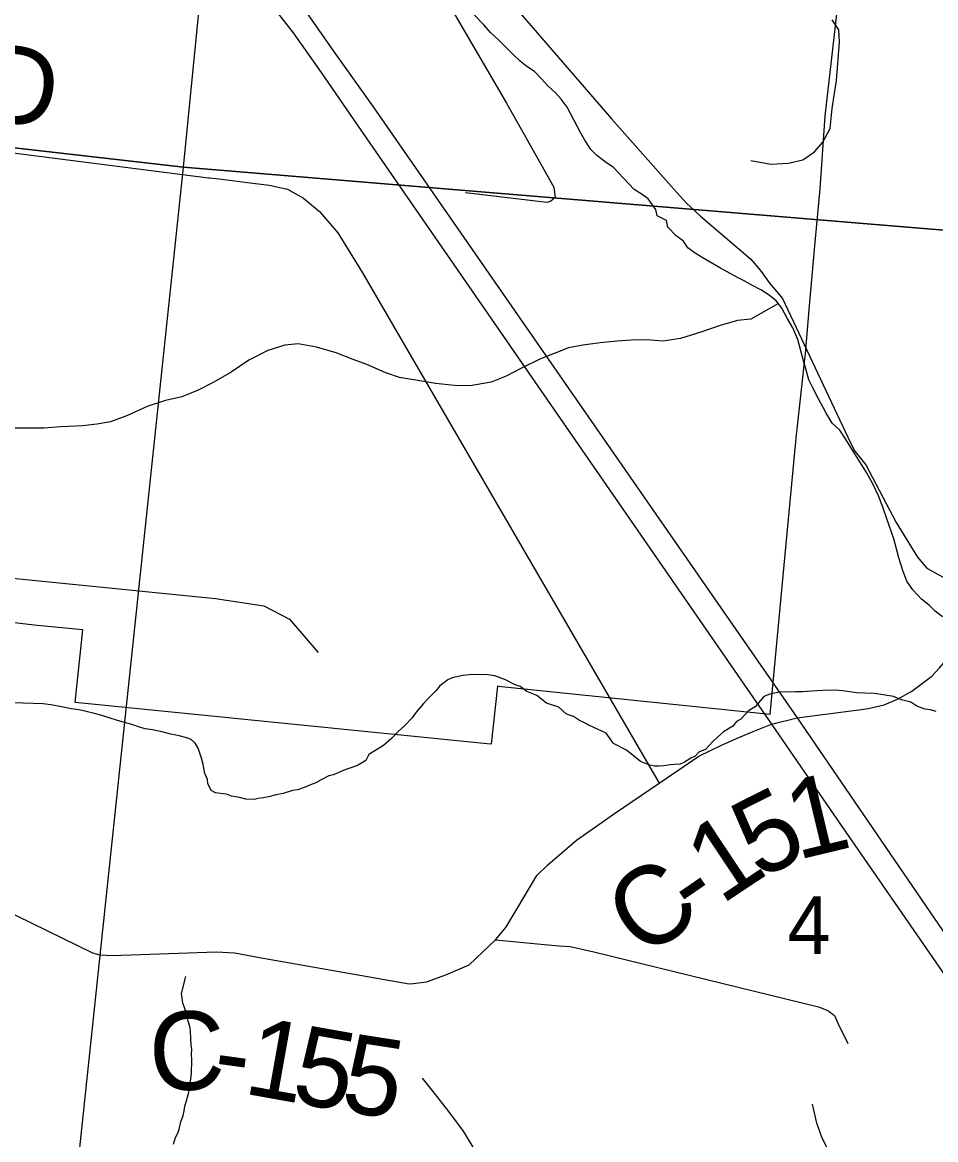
# Model space of a CAD drawing. Extents: x -8.2 to 38.5, y -0.1 to 21.9.
# Drawn here: x 2.824 to 3.486, y 18.678 to 19.487 of the extents above; entities that cross this region are included whole.
import ezdxf

# ---------------------------------------------------------------- set-up
doc = ezdxf.new("R2010")
doc.units = 0
for name, color, linetype in [('Default', 7, 'Continuous'), ('GM_X_Adjacent_County_Text', 7, 'Continuous'), ('GM_X_Airport_Location_Class_2', 7, 'Continuous'), ('GM_X_Airport_Location_Class_3', 7, 'Continuous'), ('GM_X_County_Road_Text', 7, 'Continuous'), ('GM_X_Minor_Lake', 7, 'Continuous'), ('GM_X_Minor_River', 7, 'Continuous'), ('GM_X_State_Location', 7, 'Continuous'), ('GM_X_Township_Subdivision_Text', 7, 'Continuous'), ('GM_X_Township_Text', 7, 'Continuous')]:
    doc.layers.add(name, color=color, linetype=linetype)

msp = doc.modelspace()

# ---------------------------------------------------------------- linework, layer by layer
at = {"layer": 'Default'}
for points in [[(2.16338, 20.48187), (2.16338, 19.47123), (2.94081, 19.38227), (3.04131, 20.39747)], [(2.16338, 19.47123), (2.16338, 18.47186), (2.83734, 18.40237), (2.94081, 19.38227)]]:
    msp.add_lwpolyline(points, close=True, dxfattribs=at)
msp.add_lwpolyline([(3.41379, 19.493), (3.40549, 19.41911), (3.40175, 19.36666), (3.39768, 19.32267), (3.39595, 19.30346), (3.39387, 19.27927), (3.39109, 19.24707), (3.39066, 19.24312), (3.38508, 19.19243), (3.38488, 19.19062), (3.38444, 19.18668), (3.38409, 19.18291), (3.3839, 19.18094), (3.3767, 19.10439), (3.36555, 18.98579), (3.17114, 19.0059), (3.16831, 19.00619), (3.16369, 18.96422), (3.16086, 18.9645), (2.86227, 18.99442), (2.86786, 19.04702), (2.83497, 19.05032), (2.79953, 19.05424)], dxfattribs=at)
at = {"layer": 'GM_X_Adjacent_County_Text'}
for points in [[(3.04131, 20.39747), (4.03667, 20.29136), (3.94314, 19.29912), (2.94081, 19.38227)], [(3.94314, 19.29912), (3.84833, 18.30047), (2.83734, 18.40237), (2.94081, 19.38227)]]:
    msp.add_lwpolyline(points, close=True, dxfattribs=at)
at = {"layer": 'GM_X_Airport_Location_Class_2'}
for points in [[(3.35186, 19.38711), (3.36624, 19.38455), (3.37908, 19.38506), (3.38962, 19.38763), (3.39784, 19.39328), (3.40401, 19.40047), (3.4094, 19.41024), (3.41069, 19.42488), (3.41377, 19.44518), (3.41608, 19.47292), (3.41557, 19.48166), (3.41069, 19.48911)], [(2.59965, 19.05086), (2.62209, 19.0486), (2.63274, 19.04912), (2.6407, 19.05509), (2.66855, 19.08383), (2.68355, 19.09182), (2.69711, 19.0964), (2.71187, 19.0964), (2.77842, 19.08832), (2.95204, 19.07106)], [(2.95204, 19.07106), (2.96401, 19.06987), (2.99912, 19.06443), (3.01761, 19.05493), (3.03842, 19.03078)]]:
    msp.add_lwpolyline(points, dxfattribs=at)
at = {"layer": 'GM_X_Airport_Location_Class_3'}
for points in [[(2.51015, 19.91355), (2.55411, 19.89008), (2.59469, 19.86662), (2.63548, 19.84074), (2.67343, 19.81573), (2.71422, 19.787), (2.74625, 19.76222), (2.77936, 19.73568), (2.81248, 19.70782), (2.83902, 19.6837), (2.88245, 19.6418), (2.9, 19.62338), (2.92789, 19.59381), (2.94605, 19.57206), (2.9693, 19.54486), (2.99496, 19.51218), (3.02019, 19.4795), (3.04058, 19.45077), (3.06668, 19.41304), (3.36682, 18.97876), (3.4094, 18.91703)], [(3.4094, 18.91703), (3.54394, 18.72194), (3.6115, 18.62456), (3.80034, 18.35105), (3.84376, 18.28895), (3.8839, 18.23152), (3.90386, 18.2052), (3.92843, 18.17844), (3.94926, 18.15958), (3.97164, 18.14225), (3.99927, 18.12427), (4.03722, 18.10519), (4.06573, 18.094), (4.08985, 18.08654), (4.12385, 18.07909), (4.15214, 18.07558), (4.18397, 18.07447), (4.18884, 18.07473)]]:
    msp.add_lwpolyline(points, dxfattribs=at)
at = {"layer": 'GM_X_Minor_River'}
for points in [[(3.3107, 19.32035), (3.30623, 19.3239), (3.30294, 19.32857), (3.29772, 19.33252), (3.2918, 19.33878), (3.2908, 19.34375), (3.28404, 19.34699), (3.28302, 19.35159), (3.27753, 19.35935), (3.27305, 19.36252), (3.26744, 19.36611), (3.25228, 19.38214), (3.2463, 19.38612), (3.24035, 19.39085), (3.2359, 19.39516), (3.23152, 19.40176), (3.22861, 19.40679), (3.22138, 19.4207), (3.21885, 19.42572), (3.21445, 19.43155), (3.21039, 19.43623), (3.20444, 19.44135), (3.20038, 19.44603), (3.19521, 19.45151), (3.1896, 19.45509), (3.18476, 19.45903), (3.17995, 19.46374), (3.1755, 19.46805), (3.1692, 19.47432), (3.16327, 19.47981), (3.15847, 19.48528), (3.15145, 19.49271)], [(3.49067, 19.05641), (3.48547, 19.06074), (3.48102, 19.06506), (3.47543, 19.0694), (3.46915, 19.07605), (3.46475, 19.08226), (3.46192, 19.08996), (3.45913, 19.09918), (3.4574, 19.1057), (3.45531, 19.11299), (3.45215, 19.1226), (3.45038, 19.1276), (3.44757, 19.13605), (3.44437, 19.14414), (3.44005, 19.1534), (3.4357, 19.16113), (3.42039, 19.18555), (3.41637, 19.19175), (3.4108, 19.19686), (3.40607, 19.20461), (3.40065, 19.21504), (3.39666, 19.22238), (3.39377, 19.22817), (3.39171, 19.23623), (3.38996, 19.24199), (3.38582, 19.25733), (3.38224, 19.26581), (3.37825, 19.27278), (3.37426, 19.28012), (3.37023, 19.28556), (3.36501, 19.28952), (3.35903, 19.29349), (3.35265, 19.29672), (3.34704, 19.29992), (3.34216, 19.30234), (3.33466, 19.30636), (3.32979, 19.30916), (3.3223, 19.31356), (3.31669, 19.31676), (3.3107, 19.32035)], [(3.37177, 19.28348), (3.35181, 19.27206), (3.34229, 19.27115), (3.32967, 19.26765), (3.31626, 19.26304), (3.30094, 19.25809), (3.28835, 19.25612), (3.27621, 19.25717), (3.26519, 19.25706), (3.25491, 19.25617), (3.24272, 19.25495), (3.23014, 19.25335), (3.21984, 19.25132), (3.20948, 19.24739), (3.19951, 19.24345), (3.18566, 19.23657), (3.1745, 19.23076), (3.16376, 19.22645), (3.14849, 19.22378), (3.1371, 19.22406), (3.12345, 19.22554), (3.11362, 19.2273), (3.09734, 19.22998), (3.08754, 19.23326), (3.07363, 19.2393), (3.06384, 19.24297), (3.05141, 19.24783), (3.03708, 19.25198), (3.02383, 19.25421), (3.01431, 19.2533), (3.00205, 19.24942), (2.98821, 19.24253), (2.97546, 19.23372), (2.96274, 19.22642), (2.95158, 19.22061), (2.93969, 19.21595), (2.92784, 19.2132), (2.91444, 19.20897), (2.90022, 19.20247), (2.88795, 19.19782), (2.87803, 19.19617), (2.86774, 19.1949), (2.85214, 19.19414), (2.83958, 19.1933), (2.82742, 19.19322), (2.81564, 19.19313)], [(3.48616, 18.988), (3.48202, 18.98926), (3.47823, 18.98974), (3.4722, 18.99181), (3.46771, 18.99461), (3.46091, 18.99632), (3.45527, 18.99876), (3.4477, 19.00011), (3.44126, 19.00105), (3.42835, 19.00142), (3.42494, 19.00189), (3.42191, 19.00236), (3.4185, 19.00283), (3.41281, 19.00337), (3.40368, 19.00325), (3.39606, 19.0027), (3.3892, 19.00213), (3.38426, 19.00227), (3.37931, 19.00203), (3.37589, 19.00212), (3.37246, 19.00184), (3.36558, 19.00051), (3.36134, 18.99872), (3.3586, 18.99575), (3.35506, 18.99128), (3.35004, 18.98837), (3.34455, 18.98244), (3.34146, 18.98062), (3.33871, 18.97727), (3.33214, 18.97326), (3.32746, 18.96921), (3.32395, 18.96588), (3.31925, 18.96068), (3.31425, 18.95853), (3.31151, 18.95556), (3.30842, 18.95413), (3.30378, 18.95121), (3.3007, 18.94977), (3.29651, 18.94951), (3.29346, 18.94922), (3.28888, 18.94858), (3.28507, 18.94831), (3.28203, 18.94839), (3.27787, 18.94927), (3.27185, 18.95172), (3.26181, 18.96), (3.25243, 18.96483), (3.24693, 18.97222), (3.23491, 18.97789), (3.23078, 18.97991), (3.22779, 18.98151), (3.2233, 18.9843), (3.2184, 18.98597), (3.21283, 18.99107), (3.20378, 18.99399), (3.19671, 18.99952), (3.18956, 19.00238), (3.18471, 19.00594), (3.18058, 19.00758), (3.1742, 19.01081), (3.16629, 19.0137), (3.16137, 19.01459), (3.15415, 19.0148), (3.14768, 19.0146), (3.1431, 19.01396), (3.13545, 19.01227), (3.13237, 19.01084), (3.12654, 19.00643), (3.12379, 19.00308), (3.11832, 18.99752), (3.1148, 18.99381), (3.1093, 18.98749), (3.10653, 18.98338), (3.10105, 18.97744), (3.09637, 18.97339), (3.09168, 18.96857), (3.08584, 18.9634), (3.07501, 18.95685), (3.07299, 18.95233), (3.0668, 18.9487), (3.05644, 18.94518), (3.04951, 18.94195), (3.04607, 18.94128), (3.04067, 18.93839), (3.03681, 18.93621), (3.03296, 18.9348), (3.02911, 18.933), (3.02336, 18.93126), (3.01992, 18.93059)], [(3.01992, 18.93059), (3.01302, 18.9285), (3.00805, 18.9275), (3.00231, 18.92613), (2.99849, 18.92548), (2.99505, 18.92481), (2.99199, 18.92414), (2.98591, 18.92431), (2.98138, 18.92558), (2.9757, 18.9265), (2.97194, 18.92812), (2.96777, 18.92862), (2.96398, 18.92911), (2.96098, 18.93072), (2.95846, 18.93574), (2.95816, 18.93879), (2.95637, 18.94303), (2.95503, 18.94954), (2.95401, 18.95414), (2.95155, 18.96144), (2.94936, 18.96493), (2.94639, 18.96768), (2.94338, 18.96891), (2.93771, 18.97021), (2.93166, 18.97152), (2.92524, 18.97322), (2.91844, 18.97455), (2.91314, 18.97546), (2.90823, 18.97674), (2.90409, 18.97838), (2.89918, 18.97966), (2.89314, 18.98135), (2.88711, 18.98343), (2.87994, 18.98553), (2.87541, 18.9868), (2.87126, 18.98768), (2.86748, 18.98855), (2.86332, 18.98942), (2.85953, 18.98991), (2.85121, 18.99167), (2.84629, 18.99256), (2.84288, 18.99304), (2.83909, 18.99353), (2.82465, 18.99393), (2.81781, 18.99412)], [(2.93352, 18.67444), (2.93517, 18.67935), (2.93678, 18.68235), (2.93762, 18.68537), (2.9389, 18.69067), (2.94055, 18.69519), (2.9414, 18.6986), (2.94187, 18.70201), (2.94311, 18.70578), (2.9444, 18.71108), (2.94524, 18.7141), (2.94534, 18.71791), (2.94621, 18.72169), (2.94671, 18.72625), (2.94696, 18.73538), (2.94669, 18.73958), (2.94678, 18.743), (2.94649, 18.74644), (2.94623, 18.75063), (2.94601, 18.75673), (2.94534, 18.7598), (2.94394, 18.7644), (2.94293, 18.76938), (2.94152, 18.77361), (2.94047, 18.77669), (2.93951, 18.78357), (2.94251, 18.79605)], [(3.15071, 18.67229), (3.14377, 18.68387), (3.1331, 18.6982), (3.12167, 18.71255), (3.11392, 18.72225)], [(3.40863, 18.66865), (3.4032, 18.67944), (3.39965, 18.68979), (3.39656, 18.70356)]]:
    msp.add_lwpolyline(points, dxfattribs=at)
at = {"layer": 'GM_X_State_Location'}
for points in [[(2.51015, 19.91355), (2.55411, 19.89008), (2.59469, 19.86662), (2.63548, 19.84074), (2.67343, 19.81573), (2.71422, 19.787), (2.74625, 19.76222), (2.77936, 19.73568), (2.81248, 19.70782), (2.83902, 19.6837), (2.88245, 19.6418), (2.9, 19.62338), (2.92789, 19.59381), (2.94605, 19.57206), (2.9693, 19.54486), (2.99496, 19.51218), (3.02019, 19.4795), (3.04058, 19.45077), (3.06668, 19.41304), (3.36682, 18.97876), (3.4094, 18.91703)], [(3.02994, 19.49441), (3.05011, 19.46568), (3.07819, 19.42598), (3.38547, 18.98337), (3.5583, 18.73049)], [(3.4094, 18.91703), (3.54394, 18.72194), (3.6115, 18.62456), (3.80034, 18.35105), (3.84376, 18.28895), (3.8839, 18.23152), (3.90386, 18.2052), (3.92843, 18.17844), (3.94926, 18.15958), (3.97164, 18.14225), (3.99927, 18.12427), (4.03722, 18.10519), (4.06573, 18.094), (4.08985, 18.08654), (4.12385, 18.07909), (4.15214, 18.07558), (4.18397, 18.07447), (4.18884, 18.07473)]]:
    msp.add_lwpolyline(points, dxfattribs=at)
at = {"layer": 'GM_X_Township_Subdivision_Text'}
msp.add_line((3.41509, 18.76163), (3.422, 18.7474), dxfattribs=at)
msp.add_lwpolyline([(3.42721, 19.17665), (3.43511, 19.16666), (3.45722, 19.1248), (3.47261, 19.09965), (3.4794, 19.09169), (3.49933, 19.08075)], dxfattribs=at)
at = {"layer": 'GM_X_Township_Text'}
for points in [[(3.13065, 19.53972), (3.12552, 19.52598), (3.12436, 19.5184), (3.12616, 19.51236), (3.17472, 19.42861), (3.20901, 19.36785), (3.21004, 19.36039), (3.20671, 19.35745), (3.20417, 19.35665), (3.14504, 19.36374)], [(3.16935, 19.51188), (3.2512, 19.417), (3.29401, 19.36846), (3.30509, 19.35641), (3.31547, 19.34666), (3.3515, 19.31576), (3.3585, 19.30761), (3.36548, 19.29794), (3.37469, 19.28708), (3.42407, 19.18254), (3.42721, 19.17665)], [(2.30687, 19.45137), (2.62082, 19.41662), (2.69256, 19.40868), (2.95885, 19.37465), (2.95982, 19.37454)], [(2.95982, 19.37454), (2.96858, 19.37354), (2.98712, 19.37117), (3.00301, 19.36926), (3.01621, 19.36627), (3.02781, 19.3599), (3.03933, 19.35012), (3.0526, 19.3346), (3.07047, 19.30568), (3.28537, 18.93603)], [(3.42826, 18.98891), (3.43671, 18.99005), (3.44841, 18.99269), (3.45806, 18.99698), (3.46851, 19.00255), (3.48283, 19.01358), (3.48845, 19.0195), (3.49805, 19.03068), (3.51229, 19.05387), (3.51899, 19.06482), (3.54592, 19.10886), (3.55701, 19.12796), (3.56861, 19.15159), (3.57533, 19.17764), (3.58366, 19.20743), (3.60526, 19.30742), (3.60972, 19.32806)], [(3.16692, 18.82243), (3.17435, 18.83136), (3.18228, 18.84484), (3.19692, 18.86916), (3.20471, 18.87694), (3.22564, 18.89465), (3.25306, 18.9141), (3.28537, 18.93603), (3.31405, 18.9555), (3.33056, 18.96344), (3.34323, 18.96921), (3.35358, 18.9735), (3.36682, 18.97876), (3.38547, 18.98337), (3.42615, 18.98863), (3.42826, 18.98891)], [(2.76404, 18.86726), (2.8749, 18.813), (2.88019, 18.81172), (2.88928, 18.81112), (2.96447, 18.8138), (2.97811, 18.81308), (2.99586, 18.8096), (3.10428, 18.79057), (3.10717, 18.79093), (3.11684, 18.79215), (3.131, 18.79712), (3.14787, 18.80429), (3.16692, 18.82243), (3.20245, 18.8192), (3.2131, 18.81824), (3.22106, 18.81766), (3.23803, 18.81382), (3.40095, 18.77406), (3.40771, 18.77123), (3.41256, 18.76769), (3.41509, 18.76163)]]:
    msp.add_lwpolyline(points, dxfattribs=at)

# ---------------------------------------------------------------- texts
at = {"layer": 'GM_X_County_Road_Text'}
msp.add_text('4', height=0.04186, rotation=0.00001, dxfattribs=at).set_placement((3.37839, 18.8122))
at = {"layer": 'GM_X_Minor_Lake'}
for s, height, rotation, p in [('KLEEMAN RD', 0.056818, 353.14857, (2.35615, 19.46881)), ('1', 0.05682, 13.47332, (3.38541, 18.88027)), ('5', 0.05682, 26.78374, (3.35768, 18.86582)), ('1', 0.05682, 33.61076, (3.33031, 18.8475)), ('C', 0.05682, 34.94625, (3.27358, 18.80805)), ('-', 0.05682, 34.53498, (3.31146, 18.83452)), ('C', 0.05682, 1.41693, (2.9165, 18.71316)), ('1', 0.05682, 349.86179, (2.98325, 18.71138)), ('5', 0.05682, 349.96981, (3.01782, 18.7052)), ('5', 0.05682, 351.15093, (3.05355, 18.69889)), ('-', 0.05682, 352.20908, (2.96074, 18.71445))]:
    msp.add_text(s, height=height, rotation=rotation, dxfattribs=at).set_placement(p)

doc.saveas('drawing.dxf')
